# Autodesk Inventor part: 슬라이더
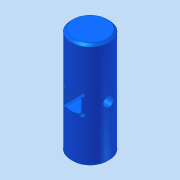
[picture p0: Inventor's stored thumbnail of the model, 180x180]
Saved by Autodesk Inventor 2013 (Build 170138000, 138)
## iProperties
Company: 한국ATC센터
Created: 2015-04
Part Number: 슬라이더
Document SubType Name: Modeling
Designer: KYOUNG IL JANG
Density: 7.85 g/cm^3
Material: 강
Author: KYOUNG IL JANG
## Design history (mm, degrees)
sketch "스케치1"
  geometry: C1 r 9 at (0, 0); 1 further point
  constraints: 1 centre point, 1 coincident
  dimensions: "d0" = 18 diameter of C1
extrude "돌출1" new body sketch "스케치1" stored distance "d1" = 50; taper "d2" = 0 deg
node "작업 평면1"
sketch "스케치3"
  geometry: L1 (4, 25)-(-4, 25); L2 (-4, 25)-(-4, -25); L3 (-4, -25)-(4, -25); L4 (4, -25)-(4, 25); 3 further points
  constraints: 8 end point, 2 midpoint, 2 parallel, 1 horizontal, 1 horizontal alignment, 1 perpendicular, 1 vertical alignment
  dimensions: "d5" = 8 distance of L1.start L1.end; "d6" = 50 distance of L1.end L2.end
extrude "돌출3" cut sketch "스케치3" stored distance "d7" = 8; taper "d8" = 0 deg
sketch "스케치4"
  geometry: 5 further points
hole "구멍1" sketch "스케치4" at (4, 4), (-4, 4), (-4, -4), (4, -4) diameter "d9" = 2; stored, may be unused: countersink angle "d13" = 90 deg, drill point angle "d15" = 118 deg; dims "d10" = 6, "d11" = 4, "d12" = 2, "d14" = 8
node "작업 평면2"
sketch "스케치5"
  geometry: 1 further point
hole "구멍2" sketch "스케치5" at (0, 0) diameter "d16" = 5; stored, may be unused: countersink angle "d20" = 90 deg, drill point angle "d22" = 118 deg; dims "d17" = 6, "d18" = 4, "d19" = 2, "d21" = 8
chamfer "모따기1" distance "d23" = 1; stored, may be unused: second distance "d24" = 2, angle "d25" = 45 deg
node "솔리드1"
mirror "대칭1"
